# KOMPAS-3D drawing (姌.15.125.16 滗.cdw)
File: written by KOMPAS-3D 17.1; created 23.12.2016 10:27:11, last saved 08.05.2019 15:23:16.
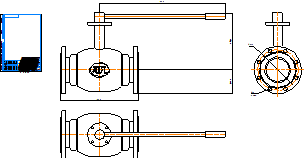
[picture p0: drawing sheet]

Sheet 1: A4, portrait

Title block, sheet 1: name: КШ.15.125.16 фф; material: Внимание! Данный продукт является объектом авторского права ООО «Торговый Дом АДЛ». / Запрещается изменение, копирование, распространение / (в том числе путем копирования на другие сайты и ресурсы в Интернете) / или любое иное использование информации и объектов без предварительного / согласия правообладателя (ООО «Торговый Дом АДЛ»).; sheets: 1; organisation: ООО "Торговый дом АДЛ"; sheet format: A4; stored path: C:\Users\tra\Desktop\2д чертежи\Шаровые краны БИВАЛ\КШ_Бивал_серия_14_15\KOMPAS_2D\КШ.15.125.16 фф.cdw

Views: Вид 1, Проекционный вид 2, Проекционный вид 3
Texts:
  Klimkovich
  ADL
Dimensions and other numbers on the sheet: 400; 645; 291,6; 122,5; 210; 18; 8 Отв.; 1:1; 1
